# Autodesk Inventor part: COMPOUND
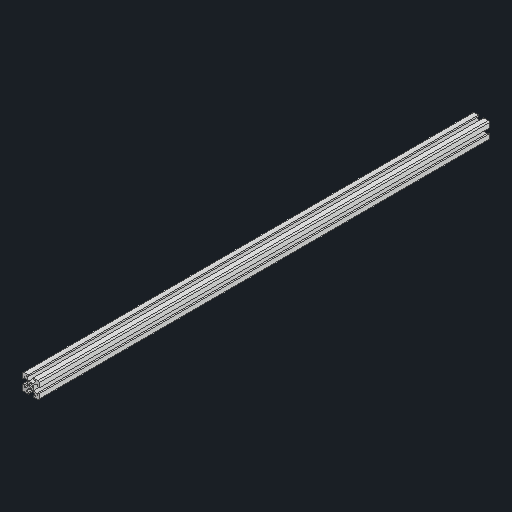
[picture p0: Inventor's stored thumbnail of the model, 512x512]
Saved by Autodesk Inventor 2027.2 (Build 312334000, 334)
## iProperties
Created: 2026-11
Part Number: COMPOUND
Material: Genérico
Document SubType Name: Modeling
Designer: Usuario
Density: 1 g/cm^3
Appearance: Valor por defecto
Author: Usuario
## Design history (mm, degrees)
feature "Base1"
sketch "Boceto1"
  geometry: L1 (-7.2, -4.9)-(-7.2, 0.6) reference; L2 (-5.7, -6.4)-(-0.2, -6.4) reference; L3 (-0.2, -4.6)-(-0.2, -6.4) reference; L4 (-2.8, -4.6)-(-0.2, -4.6) reference; L5 (0, 0)-(-2.8, -4.6) reference; L6 (5.6, 0)-(0, 0) reference; L7 (8.4, -4.6)-(5.6, 0) reference; L8 (5.8, -4.6)-(8.4, -4.6) reference; L9 (5.8, -4.6)-(5.8, -6.4) reference; L10 (5.8, -6.4)-(11.3, -6.4) reference; L11 (12.8, -4.9)-(12.8, 0.6) reference; L12 (11, 0.6)-(12.8, 0.6) reference; L13 (11, -2)-(11, 0.6) reference; L14 (6.4, 0.8)-(11, -2) reference; L15 (6.4, 6.4)-(6.4, 0.8) reference; L16 (11, 9.2)-(6.4, 6.4) reference; L17 (11, 6.6)-(11, 9.2) reference; L18 (11, 6.6)-(12.8, 6.6) reference; L19 (12.8, 6.6)-(12.8, 12.1) reference; L20 (5.8, 13.6)-(11.3, 13.6) reference; L21 (5.8, 11.8)-(5.8, 13.6) reference; L22 (8.4, 11.8)-(5.8, 11.8) reference; L23 (5.6, 7.2)-(8.4, 11.8) reference; L24 (0, 7.2)-(5.6, 7.2) reference; L25 (-2.8, 11.8)-(0, 7.2) reference; L26 (-0.2, 11.8)-(-2.8, 11.8) reference; L27 (-0.2, 11.8)-(-0.2, 13.6) reference; L28 (-5.7, 13.6)-(-0.2, 13.6) reference; L29 (-7.2, 6.6)-(-7.2, 12.1) reference; L30 (-5.4, 6.6)-(-7.2, 6.6) reference; L31 (-5.4, 9.2)-(-5.4, 6.6) reference; L32 (-0.8, 6.4)-(-5.4, 9.2) reference; L33 (-0.8, 0.8)-(-0.8, 6.4) reference; L34 (-5.4, -2)-(-0.8, 0.8) reference; L35 (-5.4, 0.6)-(-5.4, -2) reference; L36 (-5.4, 0.6)-(-7.2, 0.6) reference; A1 r 1.5 centre (-5.7, -4.9) between (-7.2, -4.9) and (-5.7, -6.4) reference; A2 r 1.5 centre (11.3, -4.9) between (11.3, -6.4) and (12.8, -4.9) reference; A3 r 1.5 centre (11.3, 12.1) between (12.8, 12.1) and (11.3, 13.6) reference; A4 r 1.5 centre (-5.7, 12.1) between (-5.7, 13.6) and (-7.2, 12.1) reference; A5 r 0.9 centre (0.6, 3.6) between (0.882, 4.455) and (0.882, 2.745) reference; A6 r 2.1 centre (2.8, 3.6) between (1.945, 5.518) and (0.882, 4.455) reference; A7 r 0.9 centre (2.8, 5.8) between (3.655, 5.518) and (1.945, 5.518) reference; A8 r 2.1 centre (2.8, 3.6) between (4.718, 4.455) and (3.655, 5.518) reference; A9 r 0.9 centre (5, 3.6) between (4.718, 2.745) and (4.718, 4.455) reference; A10 r 2.1 centre (2.8, 3.6) between (3.655, 1.682) and (4.718, 2.745) reference; A11 r 0.9 centre (2.8, 1.4) between (1.945, 1.682) and (3.655, 1.682) reference; A12 r 2.1 centre (2.8, 3.6) between (0.882, 2.745) and (1.945, 1.682) reference
extrude "Extrusión1" join sketch "Boceto1" distance "d0" = 40; taper "d1" = 0 deg
node "Sólido1"
